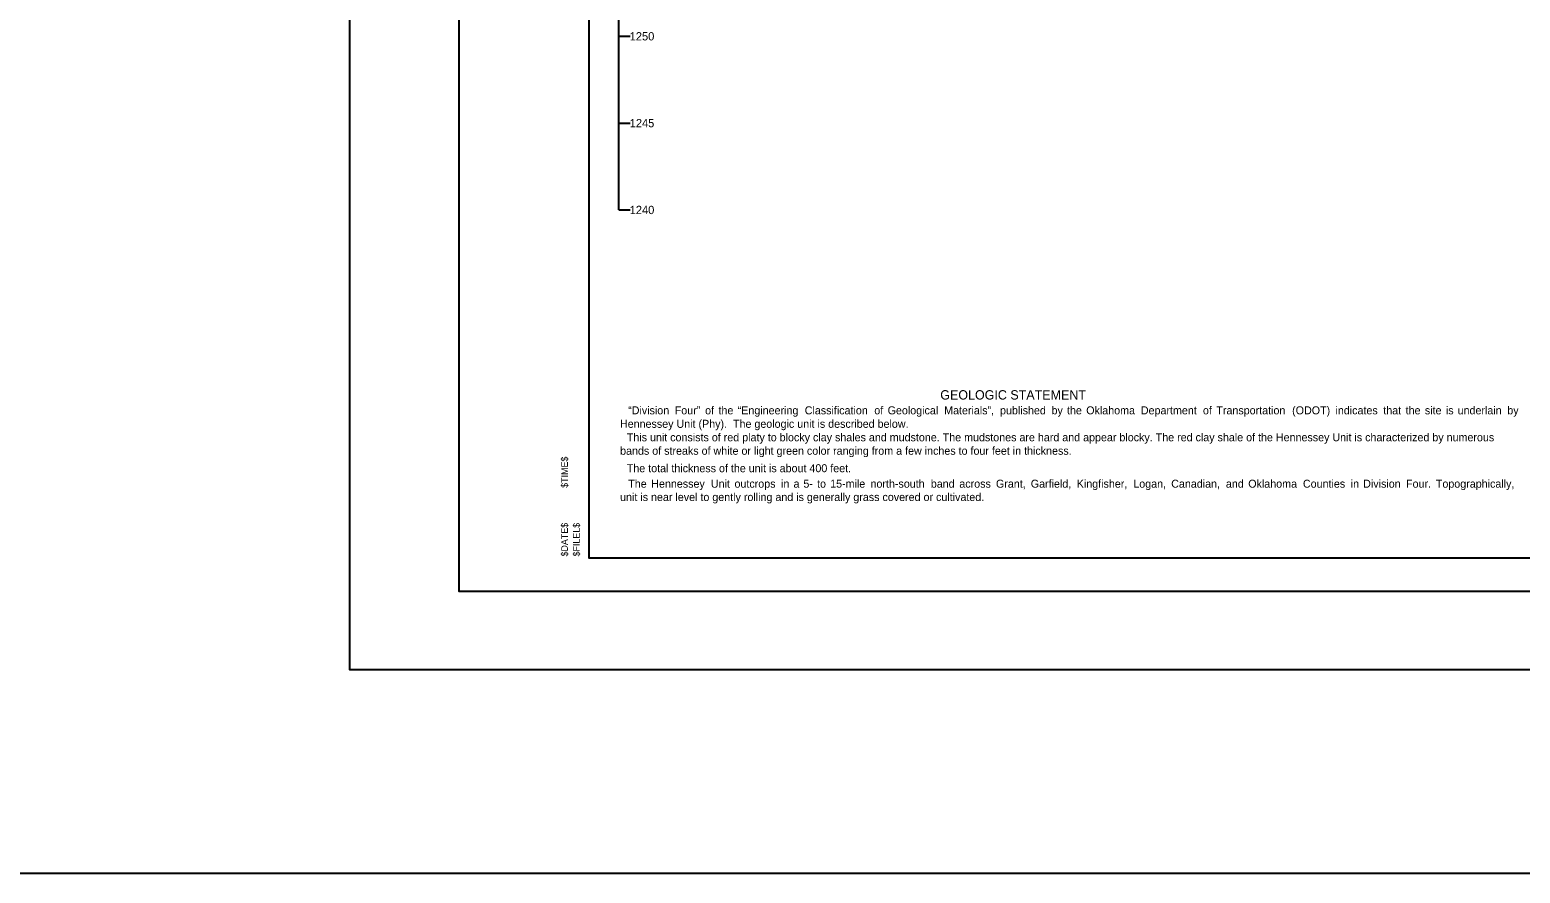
# Model space of a CAD drawing. Extents: x -2 to 138, y 24 to 58.
# Drawn here: x 43.5 to 65.85, y 26.92 to 39.57 of the extents above; entities that cross this region are included whole.
import ezdxf

# ---------------------------------------------------------------- set-up
doc = ezdxf.new("R2010")
doc.units = 0
for name, color, linetype in [('S', 7, 'Continuous'), ('SHT_Plot_Shape_Full', 7, 'Continuous'), ('SHT_Plot_Shape_Half', 7, 'Continuous'), ('SHT_Plot_Stamp', 7, 'Continuous'), ('SHT_Sheet_Border', 7, 'Continuous'), ('Text', 7, 'Continuous')]:
    doc.layers.add(name, color=color, linetype=linetype)

# ---------------------------------------------------------------- blocks, each defined once
blk = doc.blocks.new('Stamp_Plot_Stamp')
at = {"layer": 'SHT_Plot_Stamp'}
for s, p in [('$TIME$', (1.695, 1.572)), ('$DATE$', (1.695, 0.542)), ('$FILEL$', (1.873, 0.542))]:
    blk.add_text(s, height=0.1, rotation=90, dxfattribs=at).set_placement(p)

msp = doc.modelspace()

# ---------------------------------------------------------------- linework, layer by layer
msp.add_line((52.336, 36.866), (52.336, 49.887))
for points in [[(52.336, 39.47), (52.502, 39.47)], [(52.336, 38.168), (52.502, 38.168)], [(52.336, 36.866), (52.502, 36.866)]]:
    msp.add_lwpolyline(points)
at = {"layer": 'S'}
msp.add_lwpolyline([(-2.212, 26.92), (137.529, 26.92), (137.529, 58.049), (-2.212, 58.049)], close=True, dxfattribs=at)
at = {"layer": 'SHT_Plot_Shape_Full'}
msp.add_lwpolyline([(48.302, 53.971), (84.302, 53.971), (84.302, 29.971), (48.302, 29.971)], close=True, dxfattribs=at)
at = {"layer": 'SHT_Plot_Shape_Half'}
msp.add_lwpolyline([(49.939, 53.146), (83.939, 53.146), (83.939, 31.146), (49.939, 31.146)], close=True, dxfattribs=at)
at = {"layer": 'SHT_Sheet_Border'}
msp.add_lwpolyline([(51.889, 52.646), (83.389, 52.646), (83.389, 31.646), (51.889, 31.646)], close=True, dxfattribs=at)

# ---------------------------------------------------------------- block references
at = {"layer": 'SHT_Plot_Stamp'}
msp.add_blockref('Stamp_Plot_Stamp', (49.875, 31.127), dxfattribs=at)

# ---------------------------------------------------------------- texts
for s, p in [('1250', (52.497, 39.408)), ('1245', (52.497, 38.106)), ('1240', (52.497, 36.804))]:
    msp.add_text(s, height=0.124).set_placement(p)
at = {"layer": 'Text'}
for s, height, p in [('GEOLOGIC STATEMENT', 0.14, (57.153, 34.023)), ('“Division', 0.12, (52.474, 33.801)), ('Four”', 0.12, (53.172, 33.801)), ('of', 0.12, (53.627, 33.801)), ('the', 0.12, (53.828, 33.801)), ('“Engineering', 0.12, (54.116, 33.801)), ('Classification', 0.12, (55.121, 33.801)), ('of', 0.12, (56.164, 33.801)), ('Geological', 0.12, (56.364, 33.801)), ('Materials”,', 0.12, (57.211, 33.801)), ('published', 0.12, (58.049, 33.801)), ('by', 0.12, (58.821, 33.801)), ('the', 0.12, (59.053, 33.801)), ('Oklahoma', 0.12, (59.341, 33.801)), ('Department', 0.12, (60.16, 33.801)), ('of', 0.12, (61.091, 33.801)), ('Transportation', 0.12, (61.292, 33.801)), ('(ODOT)', 0.12, (62.428, 33.801)), ('indicates', 0.12, (63.078, 33.801)), ('that', 0.12, (63.795, 33.801)), ('the', 0.12, (64.13, 33.801)), ('site', 0.12, (64.418, 33.801)), ('is', 0.12, (64.733, 33.801)), ('underlain', 0.12, (64.909, 33.801)), ('by', 0.12, (65.654, 33.801)), ('Hennessey Unit (Phy).  The geologic unit is described below.', 0.12, (52.351, 33.599)), ('  This unit consists of red platy to blocky clay shales and mudstone. The mudstones are hard and appear blocky. The red clay shale of the Hennessey Unit is characterized by numerous ', 0.12, (52.364, 33.397)), ('bands of streaks of white or light green color ranging from a few inches to four feet in thickness.', 0.12, (52.353, 33.195)), ('  The total thickness of the unit is about 400 feet.', 0.12, (52.364, 32.933)), ('unit is near level to gently rolling and is generally grass covered or cultivated.  ', 0.12, (52.353, 32.501)), ('The', 0.12, (52.475, 32.701)), ('Hennessey', 0.12, (52.82, 32.701)), ('Unit', 0.12, (53.714, 32.701)), ('outcrops', 0.12, (54.068, 32.701)), ('in', 0.12, (54.766, 32.701)), ('a', 0.12, (54.953, 32.701)), ('5-', 0.12, (55.101, 32.701)), ('to', 0.12, (55.306, 32.701)), ('15-mile', 0.12, (55.502, 32.701)), ('north-south', 0.12, (56.107, 32.701)), ('band', 0.12, (57.011, 32.701)), ('across', 0.12, (57.439, 32.701)), ('Grant,', 0.12, (57.988, 32.701)), ('Garfield,', 0.12, (58.51, 32.701)), ('Kingfisher,', 0.12, (59.199, 32.701)), ('Logan,', 0.12, (60.047, 32.701)), ('Canadian,', 0.12, (60.615, 32.701)), ('and', 0.12, (61.435, 32.701)), ('Oklahoma', 0.12, (61.77, 32.701)), ('Counties', 0.12, (62.59, 32.701)), ('in', 0.12, (63.307, 32.701)), ('Division', 0.12, (63.493, 32.701)), ('Four.', 0.12, (64.136, 32.701)), ('Topographically,', 0.12, (64.583, 32.701))]:
    msp.add_text(s, height=height, dxfattribs=at).set_placement(p)

doc.saveas('drawing.dxf')
